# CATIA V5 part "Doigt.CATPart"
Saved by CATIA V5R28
Part number: Doigt
Bounding box of the stored display mesh (mm): x 0 to 152, y 0 to 40, z 0 to 16
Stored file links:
  C:\Users\8alex\Desktop\ECL\1A\PE\CATIA\Tuto\Doigt.CATPart
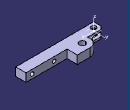
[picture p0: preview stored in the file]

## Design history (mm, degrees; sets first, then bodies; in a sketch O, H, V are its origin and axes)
AxisSystem1: origin (0, 0, 0), X (1, 0, 0), Y (0, 1, 0), Z (0, 0, 1)
Body1 (main body)
  Sketch1 on xy-plane, origin (0, 0, 0), H (1, 0, 0), V (0, 1, 0)
    line L1 (0, 0) -> (0, 14.3431)
    point P1 (0, 20)
    line L2 (5.6569, 20) -> (32, 20)
    line L3 (32, 20) -> (32, 25)
    point P3 (32, 40)
    line L4 (47, 40) -> (72, 40)
    point P4 (72, 40)
    line L5 (72, 40) -> (72, 20)
    point P5 (72, 20)
    line L6 (72, 20) -> (152, 20)
    line L7 (152, 20) -> (152, 0)
    line L8 (152, 0) -> (0, 0)
    circle A1 centre (10, 10) radius 5
    point P8 (10, 10)
    circle A2 centre (47, 25) radius 6
    point P9 (47, 25)
    line L9 (0, 14.3431) -> (5.6569, 20)
    arc A3 centre (47, 25) radius 15 from (32, 25) to (47, 40) cw
    distance L2 P3 = 20
    length L8 = 152
    length L6 = 80
    distance P8 H = 10
    distance P8 L1 = 10
    radius A1 = 5
    distance P9 L5 = 25
    distance P9 L4 = 15
    radius A2 = 6
    distance O P1 = 20
    angle L1 L9 = 45
    length L9 = 8
    distance P3 P4 = 40
    radius A3 = 15
    vertical: L1 V, L3 V, L5 V, L7 V
    horizontal: L2 H, L4 H, L6 H, L8 H
    coincidence: P5 L2, L1 P1, L2 P1, L3 P3, L4 P3
    tangency: A3 L3, A3 L4
  Pad1: profile Sketch1, direction (0, 0, 1), length 16
  Sketch2 on face of Pad1 from Sketch1.L2, origin (0, 20, 0), H (-1, 0, 0), V (0, 0, 1)
    line L1 (0, 12) -> (-22, 12)
    line L2 (-22, 12) -> (-22, 4)
    line L3 (-22, 4) -> (0, 4)
    line L4 (0, 4) -> (0, 12)
    reference projected point E1 (-5.6569, 0) from vertex [face of Pad1 from Sketch1.L9 | start face of Pad1 | face of Pad1 from Sketch1.L2]
    distance E1 L3 = 4
    length L4 = 8
    length L1 = 22
    horizontal: L1 H, L3 H
    vertical: L2 V, L4 V
  Pocket1: profile Sketch2, direction (0, -1, 0), through (limit type 6)
  Sketch3 on face of Pad1 from Sketch1.L6, origin (137.9888, 20, 8.2849), H (1, 0, 0), V (0, 0, -1)
    point P1 (2.0112, 0.2849)
    reference projected line E1 (14.0112, 8.2849) -> (14.0112, -7.7151) from edge [face of Pad1 from Sketch1.L6 | face of Pad1 from Sketch1.L7]
    reference projected line E2 (14.0112, -7.7151) -> (-65.9888, -7.7151) from edge [face of Pad1 from Sketch1.L6 | end face of Pad1]
    distance P1 E1 = 12
    distance P1 E2 = 8
  Hole1: placed by Sketch3, at (140, 20, 8) direction (0, -1, 0), diameter 6.917, depth 20, V-bottom angle 120, threaded "M8x1", thread diameter 8, thread depth 20, pitch 1
  RectPattern1: of Hole1, direction 1 instances 2, spacing 43, along face of Pad1 from Sketch1.L6 reversed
